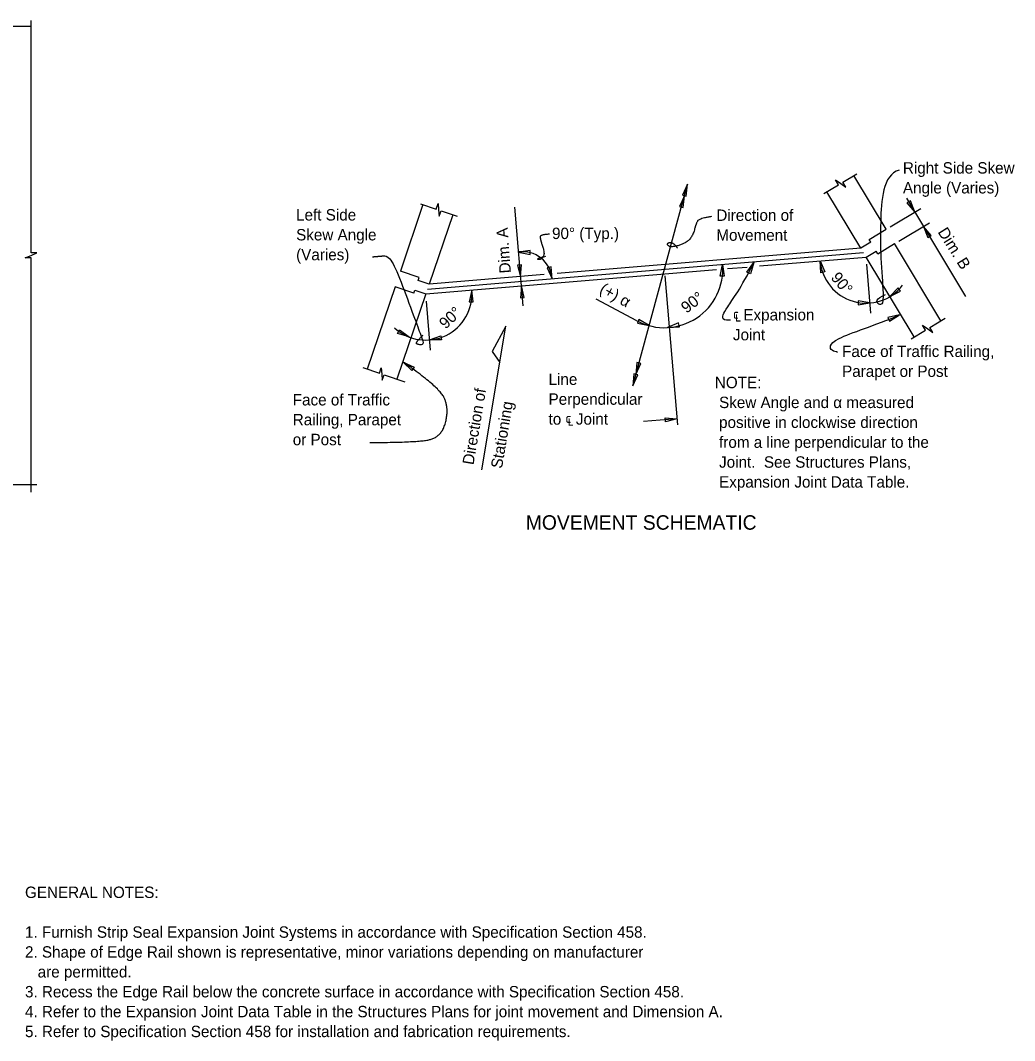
# Model space of a CAD drawing. Extents: x 0.22 to 4.79, y 0.16 to 3.12.
# Drawn here: x 2.586 to 4.788, y 0.489 to 2.747 of the extents above; entities that cross this region are included whole.
import ezdxf

# ---------------------------------------------------------------- set-up
doc = ezdxf.new("R2010")
doc.units = 0
for name, color, linetype in [('Dimension', 7, 'Continuous'), ('Miscellaneous', 7, 'Continuous'), ('SteelGirder', 7, 'Continuous'), ('SupstrConc', 7, 'Continuous'), ('TextStructures', 7, 'Continuous')]:
    doc.layers.add(name, color=color, linetype=linetype)

msp = doc.modelspace()

# ---------------------------------------------------------------- linework, layer by layer
at = {"layer": 'Dimension'}
for p, q in [((3.942, 1.938), (4.0631, 2.3838)), ((4.548, 2.3532), (4.6787, 2.1354)), ((3.699, 2.1152), (3.6807, 2.3333)), ((4.5119, 2.2898), (4.5798, 2.3306)), ((4.531, 2.2581), (4.5988, 2.2988)), ((4.4692, 2.0984), (4.4601, 2.2071)), ((4.0133, 2.1813), (4.0409, 1.8517)), ((3.4942, 2.0166), (3.4851, 2.1253)), ((3.9513, 2.0817), (3.8613, 2.1296)), ((4.0398, 1.8649), (3.9656, 1.8586))]:
    msp.add_line(p, q, dxfattribs=at)
for points in [[(2.6098, 1.7025), (2.6098, 2.2208), (2.5969, 2.2208), (2.6098, 2.2265), (2.6228, 2.2321), (2.6098, 2.2321), (2.6098, 2.7466)], [(4.365, 2.3632), (4.3976, 2.3828), (4.3909, 2.3938), (4.4024, 2.3857), (4.4139, 2.3775), (4.4072, 2.3886), (4.4379, 2.407)], [(3.4719, 2.3407), (3.5069, 2.3289), (3.511, 2.3411), (3.5122, 2.3271), (3.5134, 2.313), (3.5175, 2.3253), (3.5534, 2.3131)], [(4.5583, 2.042), (4.5904, 2.0613), (4.5838, 2.0724), (4.5953, 2.0642), (4.6067, 2.056), (4.6001, 2.0671), (4.6341, 2.0875)], [(3.608, 1.7517), (3.6611, 2.0702), (3.6308, 2.0141), (3.6476, 1.9892)], [(3.3446, 1.9782), (3.381, 1.9658), (3.3851, 1.978), (3.3863, 1.964), (3.3874, 1.95), (3.3916, 1.9622), (3.4373, 1.9467)], [(2.6228, 1.719), (2.3383, 1.719), (2.3383, 1.7025), (2.3241, 1.7345), (2.3241, 1.719), (2.0859, 1.719)]]:
    msp.add_lwpolyline(points, dxfattribs=at)
for points in [[(4.0631, 2.3838), (4.052, 2.3598), (4.0606, 2.3575)], [(4.0563, 2.3587), (4.0452, 2.3347), (4.0537, 2.3324)], [(4.5664, 2.3225), (4.5568, 2.3471), (4.5492, 2.3426)], [(4.5855, 2.2908), (4.5951, 2.2662), (4.6026, 2.2708)], [(3.689, 2.234), (3.7149, 2.2287), (3.7152, 2.2375)], [(4.3587, 2.188), (4.3571, 2.2144), (4.3673, 2.19)], [(3.6936, 2.1795), (3.6958, 2.2058), (3.687, 2.2051)], [(3.7633, 2.1747), (3.761, 2.201), (3.7525, 2.1987)], [(4.1356, 2.1808), (4.1409, 2.2066), (4.1444, 2.1805)], [(4.1947, 2.1894), (4.2104, 2.2107), (4.2026, 2.1854)], [(3.5883, 2.1234), (3.5855, 2.1496), (3.5795, 2.1239)], [(3.6953, 2.1588), (3.6931, 2.1325), (3.7019, 2.1333)], [(4.5113, 2.1354), (4.5349, 2.1473), (4.5296, 2.1544)], [(4.4673, 2.1212), (4.4414, 2.1261), (4.4412, 2.1172)], [(3.9781, 2.071), (3.9556, 2.0849), (3.9523, 2.0767)], [(4.5328, 2.0951), (4.507, 2.0892), (4.5104, 2.0811)], [(3.4466, 2.046), (3.4214, 2.0538), (3.4253, 2.0617)], [(4.0191, 2.0667), (4.0454, 2.0685), (4.0434, 2.0771)], [(3.4923, 2.0394), (3.5171, 2.0485), (3.5187, 2.0398)], [(3.4527, 1.972), (3.4338, 1.9905), (3.4577, 1.9792)], [(3.9488, 1.9631), (3.9599, 1.9871), (3.9514, 1.9894)], [(3.942, 1.938), (3.953, 1.962), (3.9445, 1.9643)], [(4.0135, 1.8671), (4.0398, 1.8649), (4.0142, 1.8583)]]:
    msp.add_lwpolyline(points, close=True, dxfattribs=at)
for centre, radius, start, end in [((3.6984, 2.1695), 0.0652, 4.5549, 98.2515), ((4.4588, 2.2229), 0.1021, 184.7968, 322.3219), ((4.012, 2.1958), 0.1293, 241.9734, 4.7968), ((3.4838, 2.1411), 0.1021, 227.2717, 4.7968)]:
    msp.add_arc(centre, radius, start, end, dxfattribs=at)
for points, degree in [([(4.5317, 2.4149), (4.4954, 2.4059), (4.489, 2.2845), (4.4911, 2.2138), (4.4988, 2.1219), (4.492, 2.1177), (4.4858, 2.1172), (4.4783, 2.1296), (4.5018, 2.1403)], 3), ([(4.1166, 2.3125), (4.089, 2.308), (4.0822, 2.2973), (4.0746, 2.2686), (4.0582, 2.2526), (4.0284, 2.2442), (4.0174, 2.2494), (4.0218, 2.2562), (4.0337, 2.2535), (4.041, 2.2425)], 2), ([(3.7577, 2.2734), (3.7385, 2.2724), (3.7363, 2.2644), (3.7471, 2.2325), (3.7427, 2.2219), (3.7382, 2.2174), (3.7319, 2.2168), (3.7316, 2.2207), (3.7498, 2.2247)], 2), ([(3.3659, 2.2234), (3.3834, 2.2249), (3.4073, 2.2269), (3.472, 2.0521), (3.4798, 2.0292), (3.4691, 2.0283), (3.459, 2.0327), (3.478, 2.0502)], 2), ([(4.1584, 2.083), (4.1533, 2.083), (4.1372, 2.0815), (4.1443, 2.1048), (4.1812, 2.1529), (4.2104, 2.2107)], 3), ([(4.3955, 2.0118), (4.3921, 2.0142), (4.3834, 2.0109), (4.3692, 2.0398), (4.4785, 2.0708), (4.5328, 2.0951)], 3), ([(3.3596, 1.8125), (3.4624, 1.8125), (3.5186, 1.8241), (3.5356, 1.8866), (3.5144, 1.9343), (3.4338, 1.9905)], 2)]:
    msp.add_open_spline(points, degree=degree, dxfattribs=at)
at = {"layer": 'Miscellaneous'}
msp.add_line((3.4874, 2.1518), (4.4528, 2.2328), dxfattribs=at)
at = {"layer": 'SteelGirder'}
msp.add_line((3.4911, 2.1625), (3.4667, 2.1708), dxfattribs=at)
for points in [[(4.4469, 2.2427), (3.775, 2.1864)], [(4.2225, 2.2031), (4.4588, 2.2229), (4.4809, 2.2361)], [(4.4689, 2.256), (4.4469, 2.2427)], [(3.4594, 2.1493), (3.4838, 2.1411), (4.1277, 2.1951)], [(4.1521, 2.1972), (4.1952, 2.2008)], [(3.7455, 2.1839), (3.4911, 2.1625)]]:
    msp.add_lwpolyline(points, dxfattribs=at)
at = {"layer": 'SupstrConc'}
for p, q in [((1.7419, 2.7339), (2.6099, 2.7339)), ((4.5029, 2.2844), (4.4316, 2.4032)), ((4.4469, 2.2427), (4.3721, 2.3674)), ((3.4775, 2.3388), (3.4275, 2.1914)), ((3.5433, 2.3165), (3.4911, 2.1625)), ((4.4654, 2.2619), (4.5029, 2.2844)), ((4.4689, 2.256), (4.4654, 2.2619)), ((4.4844, 2.2302), (4.4809, 2.2361)), ((4.4844, 2.2302), (4.5219, 2.2527)), ((4.6245, 2.0817), (4.5219, 2.2527)), ((4.5649, 2.046), (4.4588, 2.2229)), ((3.4689, 2.1774), (3.4275, 2.1914)), ((3.4667, 2.1708), (3.4689, 2.1774)), ((3.4158, 2.1568), (3.354, 1.9749)), ((3.4572, 2.1428), (3.4158, 2.1568)), ((3.4572, 2.1428), (3.4594, 2.1493)), ((3.4838, 2.1411), (3.4198, 1.9526))]:
    msp.add_line(p, q, dxfattribs=at)

# ---------------------------------------------------------------- texts
at = {"layer": 'Dimension'}
for s, height, p in [('GENERAL NOTES:', 0.0252, (2.5963, 0.8043)), ('1. Furnish Strip Seal Expansion Joint Systems in accordance with Specification Section 458.  ', 0.0252, (2.5963, 0.7163)), ('2. Shape of Edge Rail shown is representative, minor variations depending on manufacturer', 0.0252, (2.5963, 0.6723)), ('   are permitted.', 0.0252, (2.5963, 0.6283)), ('3. Recess the Edge Rail below the concrete surface in accordance with Specification Section 458.', 0.0252, (2.5963, 0.5843)), ('4. Refer to the Expansion Joint Data Table in the Structures Plans for joint movement and Dimension A.', 0.0252001, (2.5963, 0.5403)), ('5. Refer to Specification Section 458 for installation and fabrication requirements.', 0.0252, (2.5963, 0.4963))]:
    msp.add_text(s, height=height, dxfattribs=at).set_placement(p)
at = {"layer": 'TextStructures'}
for s, height, p in [('Right Side Skew ', 0.0252, (4.5402, 2.4076)), ('Angle (Varies)', 0.0252, (4.5402, 2.3636)), ('Left Side ', 0.0252, (3.1966, 2.3037)), ('Direction of ', 0.0252, (4.1271, 2.3029)), ('Skew Angle ', 0.0252, (3.1966, 2.2597)), ('90° (Typ.) ', 0.0252, (3.7633, 2.2627)), ('Movement', 0.0252, (4.1271, 2.2589)), ('(Varies)', 0.0252, (3.1966, 2.2157)), ('℄ Expansion ', 0.0252, (4.1639, 2.0825)), ('Joint', 0.0252, (4.1639, 2.0385)), ('Face of Traffic Railing, ', 0.0252, (4.4055, 2.0016)), ('Line ', 0.0252, (3.7556, 1.9399)), ('Parapet or Post', 0.0252, (4.4055, 1.9576)), ('NOTE:  ', 0.0252, (4.1238, 1.9326)), ('Face of Traffic', 0.0252, (3.1892, 1.8944)), ('Perpendicular ', 0.0252, (3.7556, 1.8959)), (' Skew Angle and α measured ', 0.0252, (4.1238, 1.8886)), ('Railing, Parapet', 0.0252, (3.1892, 1.8504)), ('to ℄ Joint', 0.0252, (3.7556, 1.8519)), (' positive in clockwise direction ', 0.0252, (4.1238, 1.8446)), ('or Post', 0.0252, (3.1892, 1.8064)), (' from a line perpendicular to the ', 0.0252, (4.1238, 1.8006)), (' Joint.  See Structures Plans, ', 0.0252, (4.1238, 1.7566)), (' Expansion Joint Data Table.', 0.0252, (4.1238, 1.7126)), ('MOVEMENT SCHEMATIC', 0.032, (3.7051, 1.6194))]:
    msp.add_text(s, height=height, dxfattribs=at).set_placement(p)
for s, rotation, p in [('Dim. A', 94.3896, (3.6724, 2.1877)), ('Dim. B', 302.1391, (4.6164, 2.2784)), ('90°', 309.7565, (4.3793, 2.1766)), ('(+) α', 330.5011, (3.8665, 2.1453)), ('90°', 37.1776, (4.061, 2.0973)), ('90°', 43.1571, (3.5276, 2.0621)), ('Direction of', 80.5333, (3.5894, 1.7617)), ('Stationing', 80.5333, (3.6524, 1.7536))]:
    msp.add_text(s, height=0.0252, rotation=rotation, dxfattribs=at).set_placement(p)

doc.saveas('drawing.dxf')
